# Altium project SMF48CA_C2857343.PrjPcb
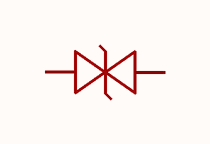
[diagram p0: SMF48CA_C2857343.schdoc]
1 sheet, 1 parts. Net scope: global (net labels, ports and power ports of the same name join across sheets).

## Sheet SMF48CA_C2857343.schdoc
size 127 x 101 mm

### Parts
D?  smf48ca_c2857343  [SMF_L2.9-W1.9-LS3.9-BI]  (value not drawn)

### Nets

Not connected (* = marked no-connect by the designer): D? 1(C) 2(A)

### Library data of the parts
D? = smf48ca_c2857343: 极性:双向;反向截止电压(Vrwm):48V;钳位电压:77.4V;峰值脉冲电流(Ipp):2.6A;峰值脉冲功率(Ppp):200W@10/1000us;击穿电压(VBR):53.3V;; Manufacturer: JSMSEMI(杰盛微); AddInBom: yes; ModelId: 9b190ad72b2a4f2384918ea07687d3cf; ModelName: DO-219AB_L2.8-W1.8-H1.0-LS3.7; ModelTransform: 145.669,70.866,0,0,0,0,0,0,0; Polarity: 双向; Reverse Stand-Off Voltage (Vrwm): 48V; Clamping Voltage: 77.4V; Peak Pulse Current (Ipp): 2.6A; Voltage - Breakdown: 53.3V; Reverse Leakage Current (Ir): 1uA; Number of Channels: 单路; Type: TVS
